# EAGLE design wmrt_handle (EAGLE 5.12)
TP_SIGNAL_NAME: ESD
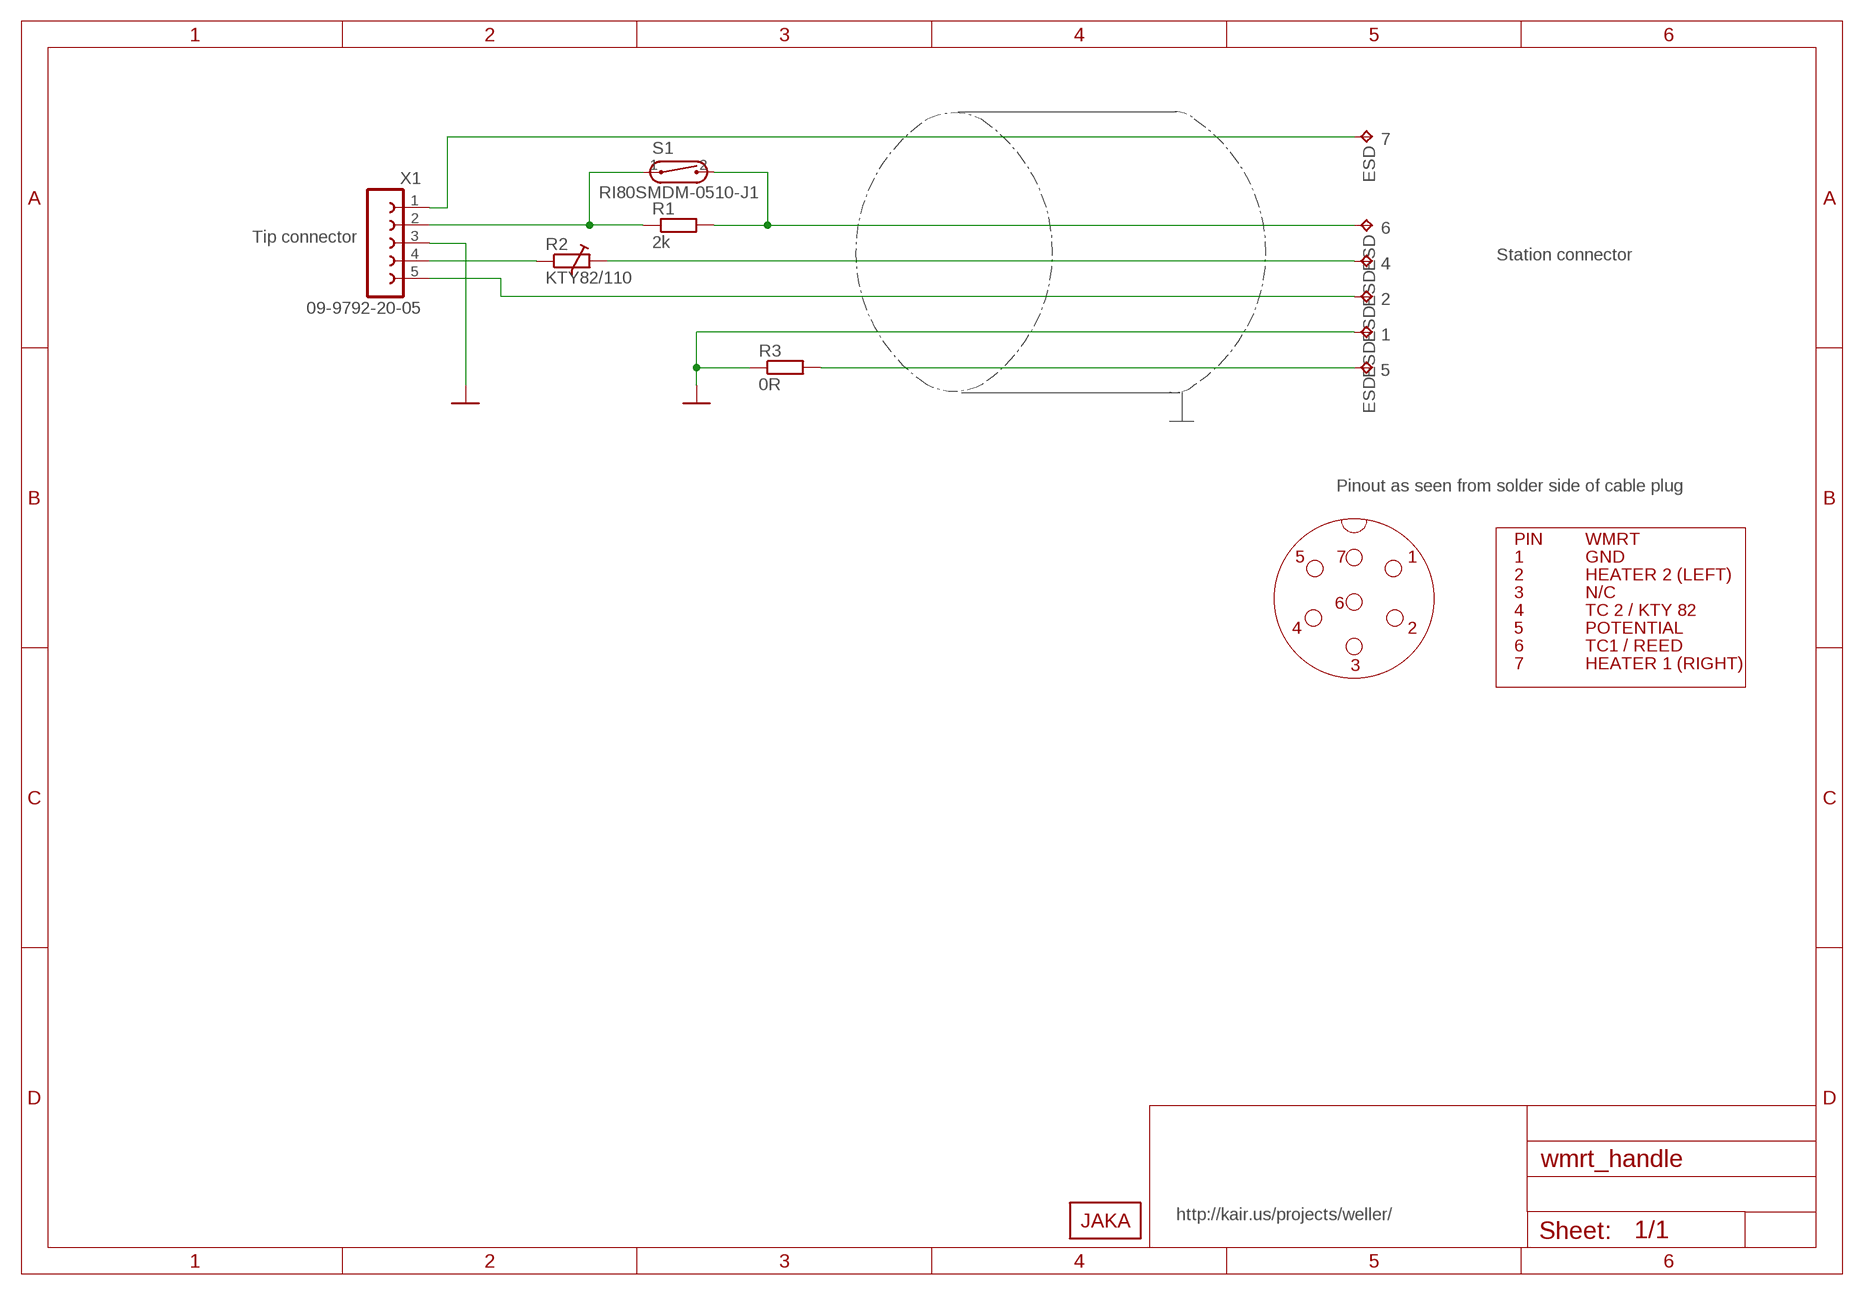
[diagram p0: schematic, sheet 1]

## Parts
1  TESTPOINTTH_1MM3_ROUND  [P1-13-R]
2  TESTPOINTTH_1MM3_ROUND  [P1-13-R]
4  TESTPOINTTH_1MM3_ROUND  [P1-13-R]
5  TESTPOINTTH_1MM3_ROUND  [P1-13-R]
6  TESTPOINTTH_1MM3_ROUND  [P1-13-R]
7  TESTPOINTTH_1MM3_ROUND  [P1-13-R]
R1  2k  R-EU_R0805  [R0805]
R2  KTY82/110  [SOT-23]
R3  0R  R-EU_R0805  [R0805]
S1  RI80SMDM-0510-J1  [RI-80_SMDM_J-1]
U$1  JAKA_LOGO_SILK_NANO  [JAKA_SILK_NANO]
X1  09-9792-20-05  [09-9792-20-05_BINDER]

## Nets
GND: 1.TP R3.1 X1.3
N$1: 4.TP R2.2
N$2: R2.1 X1.4
N$3: 6.TP R1.2 S1.2
N$4: R1.1 S1.1 X1.2
N$5: 2.TP X1.5
N$6: 7.TP X1.1
N$7: 5.TP R3.2

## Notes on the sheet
- Tip connector
- Station connector
- Pinout as seen from solder side of cable plug
- PIN | WMRT
- 5 | 7 | 1 | 1 | GND
- 2 | HEATER 2 (LEFT)
- 3 | N/C
- 6
- 4 | TC 2 / KTY 82
- 4 | 2 | 5 | POTENTIAL
- 6 | TC1 / REED
- 3 | 7 | HEATER 1 (RIGHT)
- http://kair.us/projects/weller/

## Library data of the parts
1 2 4-7 = omat:TESTPOINT
R1 R3 = omat:R-EU_: RESISTOR, European symbol
R2 = omat:KTY82
S1 = omat:RI80SMDM
U$1 = omat:JAKA_LOGO
X1 = omat:09-9792-20-05: Binder 09-9792-20-05 Female 5-pin socket, Snap-in IP40 series, dip solder termination

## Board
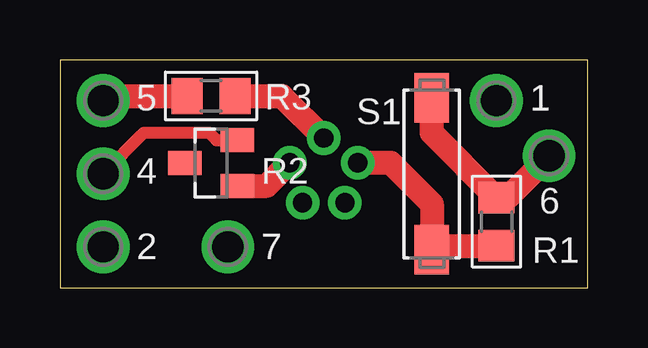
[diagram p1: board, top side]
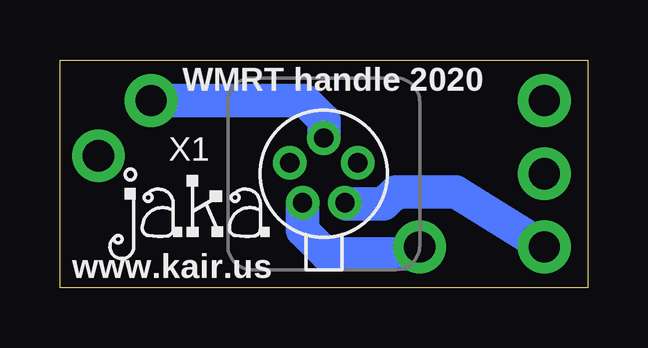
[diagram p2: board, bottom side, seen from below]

Size 22 x 9.5 mm. Coordinates in mm from the lower left corner, seen from the top.
Outline: 0,0 22,0 22,9.5 0,9.5 0,0
Copper layers (1*16): Top 0.035mm / dielectric 1.1mm / Bottom 0.035mm
Design rules "j_ace *": minimum track width 0.3mm, minimum drill 0.6mm, track to track 0.3mm, track to pad 0.3mm, pad to pad 0.3mm, via to via 0.3mm, smd to smd 0mil, copper to edge 0.5mm, drill to drill 0.25mm, minimum pad ring 0.3mm, minimum via ring 0.3mm, stop-mask expansion 2mil, vias tented up to drill 100mil, thermal gap 10mil

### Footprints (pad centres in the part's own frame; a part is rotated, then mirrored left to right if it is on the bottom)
P1-13-R = drill 1.3 pad 2.2 round: TP 0,0
R0805 = smd 1.3 x 1.5: 1 -1,0; 2 1,0
SOT-23 = smd 1 x 1.4: 1 -0.95,-1.1; 2 0.95,-1.1; 3 0,1.1
RI-80_SMDM_J-1 = smd 2.06 x 1.45: 1 -3.16,0; 2 3.16,0
09-9792-20-05_BINDER = drill 0.8 pad 1.4 round: 1 -0.88,-1.21; 2 -1.42,0.46; 3 0,1.49; 4 1.42,0.46; 5 0.88,-1.21

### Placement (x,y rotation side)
1  18.2,7.8 0 top
2  1.8,1.7 0 top
4  1.8,4.75 0 top
5  1.8,7.8 0 top
6  20.4,5.5 0 top
7  7,1.7 0 top
R1  18.2,2.75 90 top
R2  6.3,5.2 90 top
R3  6.3,8 180 top
S1  15.5,4.75 90 top
U$1  16.63,3.07 0 bottom
X1  11,4.75 0 bottom

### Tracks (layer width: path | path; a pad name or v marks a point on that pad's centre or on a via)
GND
  Top 1: R3.1 9.24,8 X1.3
  Bottom 1.4: X1.3 11,7 11.8,7.8 1.TP
N$1
  Top 0.5: R2.2 6.53,6.15 6.22,6.46 3.51,6.46 4.TP
N$2
  Top 1: R2.1 8.62,4.25 X1.4
N$3
  Top 1: S1.2 15.5,6.45 R1.2 18.65,3.75 6.TP
N$4
  Top 1: X1.2 13.79,5.21 15.5,3.5 S1.1 15.66,1.75 R1.1
N$5
  Bottom 1.4: 2.TP 5.5,4 8,4 8.52,3.48 10.06,3.48 X1.5
N$6
  Bottom 1.4: X1.1 11.88,2.38 10.9,1.4 7.3,1.4 7.TP
N$7
  Top 1: R3.2 2,8 5.TP

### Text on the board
bPlace: WMRT handle 2020 | www.kair.us
_tsilk: 5 | R3 | S1 | 1 | 4 | R2 | 6 | 2 | 7 | R1
_bsilk: WMRT handle 2020 | ESD | GND | TC2 | X1 | TC1 | HT1 | HT2 | www.kair.us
